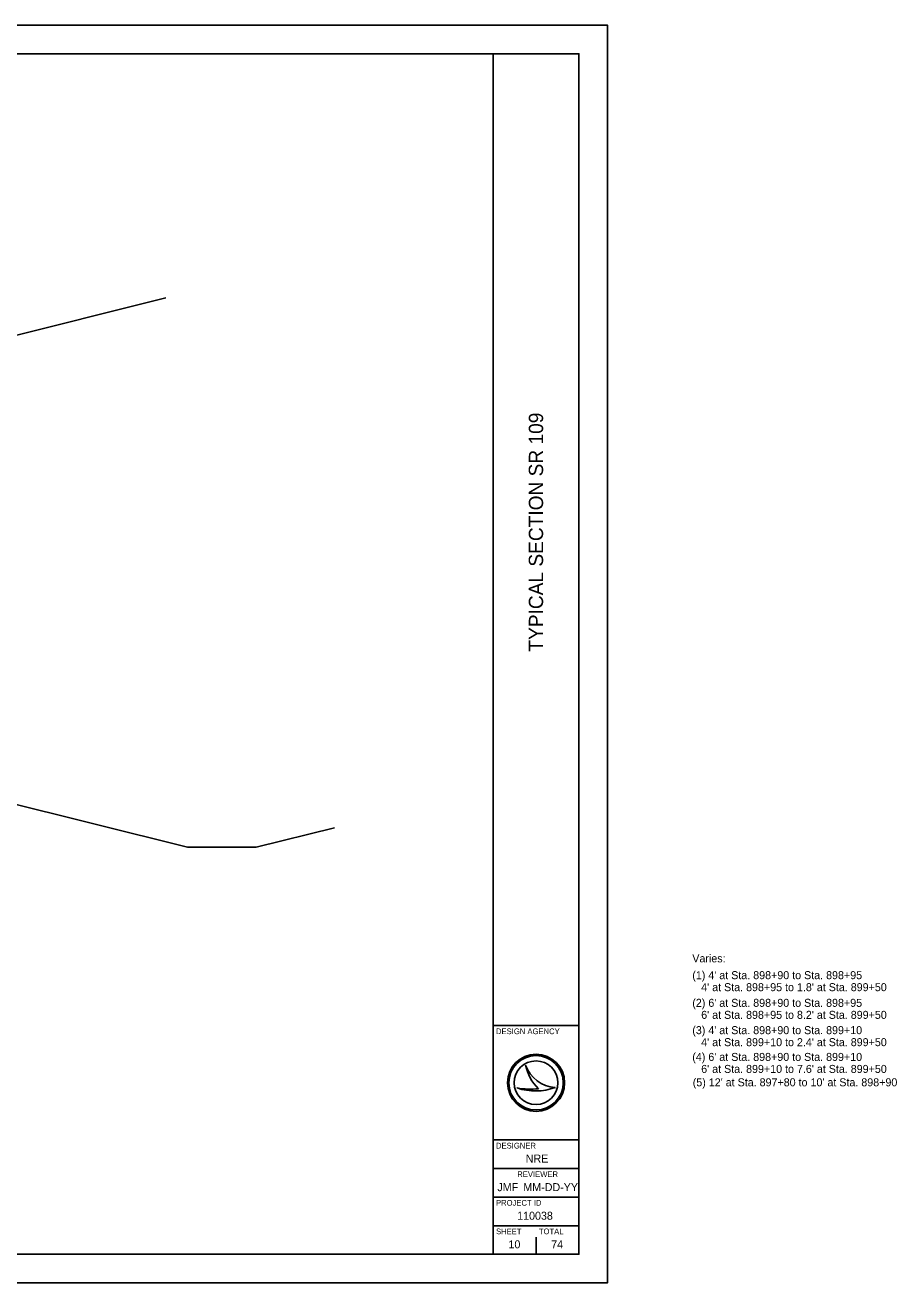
# Model space of a CAD drawing. Extents: x 0 to 195, y 0 to 110.
# Drawn here: x 119.1 to 195.3, y 0 to 110 of the extents above; entities that cross this region are included whole.
import ezdxf

# ---------------------------------------------------------------- set-up
doc = ezdxf.new("R2010")
doc.units = 0
for name, color, linetype in [('SH_Border', 7, 'Continuous'), ('SH_Cut_Line', 7, 'Continuous'), ('SH_Data', 7, 'Continuous'), ('SH_Text', 7, 'Continuous'), ('XS_X_Ground_Line', 7, 'Continuous')]:
    doc.layers.add(name, color=color, linetype=linetype)

msp = doc.modelspace()

# ---------------------------------------------------------------- linework, layer by layer
at = {"layer": 'SH_Border'}
for p, q in [((160, 2.5), (160, 107.5)), ((160, 22.5), (167.5, 22.5)), ((160, 12.5), (167.5, 12.5)), ((160, 10), (167.5, 10)), ((160, 7.5), (167.5, 7.5)), ((160, 5), (167.5, 5))]:
    msp.add_line(p, q, dxfattribs=at)
msp.add_lwpolyline([(7.5, 107.5), (167.5, 107.5), (167.5, 2.5), (7.5, 2.5)], close=True, dxfattribs=at)
at = {"layer": 'SH_Cut_Line'}
msp.add_lwpolyline([(0, 0), (170, 0), (170, 110), (0, 110)], close=True, dxfattribs=at)
at = {"layer": 'SH_Data'}
for p, q in [((162.84, 19.05), (162.84, 19.05)), ((162.09, 17.05), (162.09, 17.05)), ((163.75, 17.5), (163.75, 17.5)), ((165.44, 17.09), (165.44, 17.09)), ((161.87, 3.38), (161.87, 3.38)), ((163.75, 2.5), (163.75, 4))]:
    msp.add_line(p, q, dxfattribs=at)
for radius in [2.5, 2.38, 2.38, 1.91]:
    msp.add_circle((163.75, 17.5), radius, dxfattribs=at)
for centre, radius, start, end in [((165.58, 19.99), 2.9, 198.9257, 198.9319), ((166.73, 19.85), 3.98, 191.6379, 191.6421), ((165.58, 19.99), 2.9, 198.9319, 267.1657), ((166.73, 19.85), 3.98, 191.6421, 226.0947), ((163.7, 21.85), 5.07, 251.4576, 290.0832), ((163.24, 23.27), 6.33, 259.4964, 259.4995), ((163.7, 21.85), 5.07, 251.4527, 251.4576), ((163.24, 23.27), 6.33, 259.4995, 276.6672)]:
    msp.add_arc(centre, radius, start, end, dxfattribs=at)
at = {"layer": 'XS_X_Ground_Line'}
for p, q in [((115.85, 82.26), (131.36, 86.14)), ((116.88, 42.2), (133.27, 38.1)), ((139.27, 38.1), (146.11, 39.81)), ((139.27, 38.1), (133.27, 38.1))]:
    msp.add_line(p, q, dxfattribs=at)

# ---------------------------------------------------------------- texts
at = {"layer": 'SH_Data'}
msp.add_text('TYPICAL SECTION SR 109', height=1.25, rotation=90, dxfattribs=at).set_placement((164.37, 55.21))
for s, height, p in [('DESIGN AGENCY', 0.5, (160.25, 21.75)), ('DESIGNER', 0.5, (160.25, 11.75)), ('NRE', 0.7, (162.85, 10.52)), ('REVIEWER', 0.5, (162.11, 9.25)), ('JMF', 0.7, (160.37, 8.02)), ('MM-DD-YY', 0.7, (162.64, 8.02)), ('PROJECT ID', 0.5, (160.25, 6.75)), ('110038', 0.7, (162.1, 5.52)), ('SHEET', 0.5, (160.25, 4.25)), ('TOTAL', 0.5, (164, 4.25)), ('10', 0.7, (161.34, 3.02)), ('74', 0.7, (165.08, 3.02))]:
    msp.add_text(s, height=height, dxfattribs=at).set_placement(p)
at = {"layer": 'SH_Text'}
for s, p in [('Varies:                      ', (177.42, 28.03)), ("(1) 4' at Sta. 898+90 to Sta. 898+95", (177.42, 26.56)), ("   4' at Sta. 898+95 to 1.8' at Sta. 899+50            ", (177.42, 25.51)), ("(2) 6' at Sta. 898+90 to Sta. 898+95", (177.42, 24.14)), ("   6' at Sta. 898+95 to 8.2' at Sta. 899+50  ", (177.42, 23.09)), ("(3) 4' at Sta. 898+90 to Sta. 899+10", (177.42, 21.75)), ("   4' at Sta. 899+10 to 2.4' at Sta. 899+50  ", (177.42, 20.7)), ("(4) 6' at Sta. 898+90 to Sta. 899+10", (177.42, 19.41)), ("   6' at Sta. 899+10 to 7.6' at Sta. 899+50  ", (177.42, 18.36)), ("(5) 12' at Sta. 897+80 to 10' at Sta. 898+90", (177.46, 17.19))]:
    msp.add_text(s, height=0.7, dxfattribs=at).set_placement(p)

doc.saveas('drawing.dxf')
